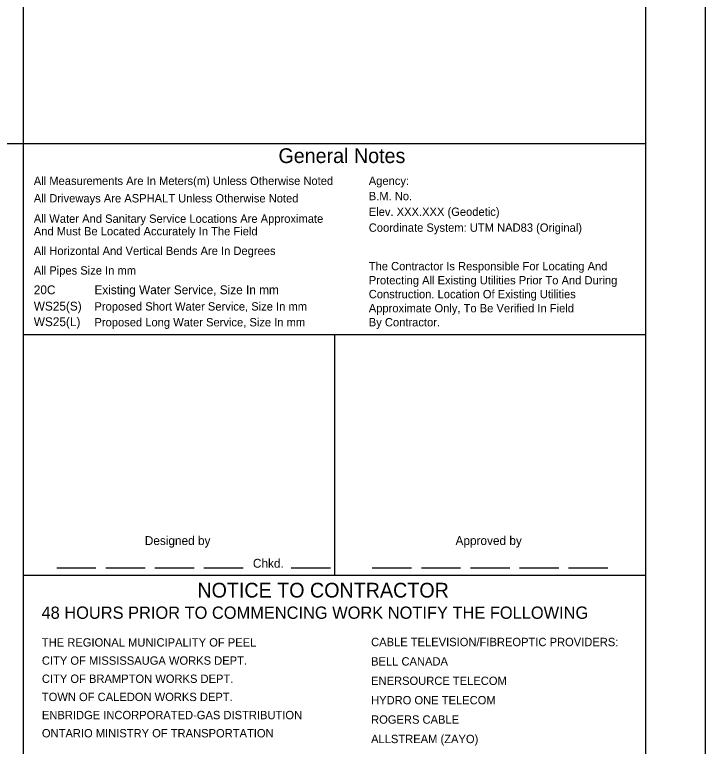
# Model space of a CAD drawing. Extents: x 613360 to 613780, y 4825621 to 4825911.
# Drawn here: x 613709.9 to 613780.3, y 4825694.7 to 4825769.2 of the extents above; entities that cross this region are included whole.
import ezdxf

# ---------------------------------------------------------------- set-up
doc = ezdxf.new("R2010")
doc.units = 0
for name, color, linetype in [('G-ANNO-STMP', 7, 'Continuous'), ('G-ANNO-TEXT', 7, 'Continuous'), ('G-TTLB-OTLN', 7, 'Continuous'), ('G-TTLB-OTLN-PB', 7, 'Continuous')]:
    doc.layers.add(name, color=color, linetype=linetype)

msp = doc.modelspace()

# ---------------------------------------------------------------- linework, layer by layer
at = {"layer": 'G-ANNO-STMP'}
for p, q in [((613714.165, 4825712.893), (613718.165, 4825712.892)), ((613719.165, 4825712.892), (613723.165, 4825712.892)), ((613724.165, 4825712.892), (613728.165, 4825712.892)), ((613729.165, 4825712.892), (613733.165, 4825712.892)), ((613738.073, 4825712.892), (613742.073, 4825712.892)), ((613746.328, 4825712.892), (613750.328, 4825712.892)), ((613751.328, 4825712.892), (613755.328, 4825712.892)), ((613756.328, 4825712.892), (613760.328, 4825712.892)), ((613761.328, 4825712.892), (613765.328, 4825712.892)), ((613766.328, 4825712.892), (613770.328, 4825712.892))]:
    msp.add_line(p, q, dxfattribs=at)
at = {"layer": 'G-TTLB-OTLN'}
for p, q in [((613710.777, 4825623.508), (613710.777, 4825815.929)), ((613380.085, 4825756.108), (613774.178, 4825756.108)), ((613774.178, 4825736.624), (613710.777, 4825736.624)), ((613742.478, 4825736.624), (613742.478, 4825712.108)), ((613774.178, 4825712.108), (613710.777, 4825712.108))]:
    msp.add_line(p, q, dxfattribs=at)
msp.add_lwpolyline([(613380.085, 4825892.077), (613774.178, 4825892.077), (613774.178, 4825623.508), (613380.085, 4825623.508)], close=True, dxfattribs=at)
at = {"layer": 'G-TTLB-OTLN-PB'}
msp.add_lwpolyline([(613359.578, 4825620.908), (613780.27, 4825620.908), (613780.27, 4825894.677), (613359.578, 4825894.677)], close=True, dxfattribs=at)

# ---------------------------------------------------------------- texts
at = {"layer": 'G-ANNO-STMP'}
for s, p in [('Designed by', (613723.139, 4825715.207)), ('Approved by', (613754.806, 4825715.207)), ('Chkd.', (613734.158, 4825712.892))]:
    msp.add_text(s, height=0.9, dxfattribs=at).set_placement(p)
at = {"layer": 'G-ANNO-TEXT'}
for s, height, p in [('General Notes', 1.5, (613736.76, 4825754.107)), ('All Measurements Are In Meters(m) Unless Otherwise Noted', 0.85, (613711.826, 4825751.874)), ('All Driveways Are ASPHALT Unless Otherwise Noted', 0.85, (613711.826, 4825750.095)), ('All Water And Sanitary Service Locations Are Approximate', 0.85, (613711.826, 4825748.02)), ('And Must Be Located Accurately In The Field ', 0.85, (613711.826, 4825746.745)), ('All Horizontal And Vertical Bends Are In Degrees', 0.85, (613711.826, 4825744.745))]:
    msp.add_text(s, height=height, rotation=360, dxfattribs=at).set_placement(p)
for s, height, p in [('Agency: ', 0.85, (613745.965, 4825751.874)), ('B.M. No. ', 0.85, (613745.965, 4825750.321)), ('Elev. XXX.XXX (Geodetic)', 0.85, (613745.965, 4825748.721)), ('Coordinate System: UTM NAD83 (Original)', 0.85, (613745.965, 4825747.107)), ('All Pipes Size In mm', 0.85, (613711.826, 4825742.745)), ('The Contractor Is Responsible For Locating And ', 0.85, (613745.965, 4825743.182)), ('Protecting All Existing Utilities Prior To And During ', 0.85, (613745.965, 4825741.75)), ('20C  ', 0.9, (613711.826, 4825740.745)), ('Existing Water Service, Size In mm', 0.9, (613718.006, 4825740.749)), ('Construction. Location Of Existing Utilities', 0.85, (613745.965, 4825740.334)), ('WS25(S)', 0.9, (613711.826, 4825739.085)), ('Proposed Short Water Service, Size In mm', 0.85, (613718.006, 4825739.081)), ('Approximate Only, To Be Verified In Field ', 0.85, (613745.965, 4825738.902)), ('WS25(L)', 0.9, (613711.826, 4825737.495)), ('Proposed Long Water Service, Size In mm', 0.85, (613718.006, 4825737.47)), ('By Contractor.', 0.85, (613745.965, 4825737.47)), ('NOTICE TO CONTRACTOR', 1.5, (613728.497, 4825709.856)), ('48 HOURS PRIOR TO COMMENCING WORK NOTIFY THE FOLLOWING', 1.25, (613712.613, 4825707.688)), ('THE REGIONAL MUNICIPALITY OF PEEL', 0.85, (613712.651, 4825704.86)), ('CABLE TELEVISION/FIBREOPTIC PROVIDERS:', 0.85, (613746.202, 4825704.902)), ('CITY OF MISSISSAUGA WORKS DEPT.', 0.85, (613712.651, 4825703.01)), ('BELL CANADA', 0.85, (613746.202, 4825702.927)), ('CITY OF BRAMPTON WORKS DEPT.', 0.85, (613712.651, 4825701.16)), ('ENERSOURCE TELECOM', 0.85, (613746.202, 4825700.952)), ('TOWN OF CALEDON WORKS DEPT.', 0.85, (613712.651, 4825699.31)), ('HYDRO ONE TELECOM', 0.85, (613746.202, 4825698.977)), ('ENBRIDGE INCORPORATED-GAS DISTRIBUTION', 0.85, (613712.651, 4825697.46)), ('ROGERS CABLE', 0.85, (613746.202, 4825697.002)), ('ONTARIO MINISTRY OF TRANSPORTATION', 0.85, (613712.651, 4825695.61)), ('ALLSTREAM (ZAYO)', 0.85, (613746.202, 4825695.027))]:
    msp.add_text(s, height=height, dxfattribs=at).set_placement(p)

doc.saveas('drawing.dxf')
